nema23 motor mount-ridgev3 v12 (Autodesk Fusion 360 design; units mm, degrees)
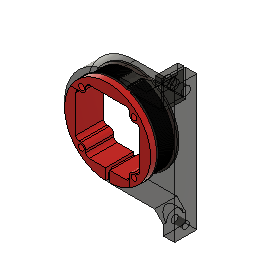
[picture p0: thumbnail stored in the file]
parameter "d58" = -1
parameter "d59" = -1
parameter "d60" = -1
parameter "d61" = -1
parameter "d62" = 4
parameter "d63" = 25.5
parameter "d66" = 16.5 (= "d67")
parameter "d67" = 16.5
parameter "d68" = 3
parameter "d81" = 16.5 (= "d67")
parameter "d89" = 28.5
parameter "d93" = 23.5
sketch "Sketch1" plane through (0, 0, 37.5) normal (0, 0, 1) x axis (1, 0, 0)
  line L1 (45, -43.5) -> (0, -43.5)
  line L2 (45, -60.5) -> (45, -43.5)
  line L3 (55, -60.5) -> (45, -60.5)
  line L4 (45, 35.8891) -> (45, 60.5)
  line L5 (55, 60.5) -> (45, 60.5)
  line L6 (55, -60.5) -> (55, 60.5)
  line L7 (43, 37) -> (0, 37)
  line L8 (43, 60.5) -> (43, 37)
  line L9 (38, 60.5) -> (43, 60.5)
  line L10 (38, 43.5) -> (38, 60.5)
  line L11 (45, 35.8891) -> (8.9984, 35.8891)
  line L12 (44, 56) -> (44, 55)
  line L13 (38, 43.5) -> (0, 43.5)
  circle C1 centre (0, 0) radius 38.5
  circle C2 centre (0, 0) radius 37
  arc A1 centre (0, 0) radius 43.5 clockwise from (24.5809, 35.8891) to (22.8747, 37)
  point P1 (0, 0)
  point P2 (0, 0)
  point P4 (0, 43.5)
  point P5 (0, -43.5)
  point P12 (0, 37)
  point P20 (24.5809, 35.8891)
  point P21 (22.8747, 37)
  point P22 (8.9984, 35.8891)
  point P7 (45, -60.5)
  point P8 (55, -60.5)
  point P13 (43, 37)
  point P6 (45, -43.5)
  point P3 (0, 0)
  point P10 (55, 60.5)
  point P9 (45, 60.5)
  point P14 (43, 60.5)
  point P15 (38, 60.5)
  coincident P1 P2
  coincident P4 A1
  horizontal L13
  coincident P5 A1
  horizontal L1
  perpendicular L1 L2
  perpendicular L2 L3
  perpendicular L4 L13
  perpendicular L4 L5
  perpendicular L3 L6
  coincident C2 P12
  horizontal L7
  perpendicular L7 L8
  perpendicular L8 L9
  perpendicular L10 L13
  parallel L7 L11
  coincident L11 P20
  coincident L7 P21
  coincident C2 P22
  dimension "d1" diameter C1 = 77
  dimension "d2" diameter A1 = 87
  dimension "d3" distance P7 P8 = 10
  dimension "d4" diameter C2 = 74
  dimension "d15" distance P12 P13 = 43
  dimension "d50" distance P6 P7 = 17
  dimension "d214" distance P3 L1 = 43.5
  dimension "d216" distance L1 L13 = 87 (= "d214 * 2")
  dimension "d217" distance P8 P10 = 121 (= "d216 + ( d50 * 2 )")
  dimension "d218" distance L3 L9 = 121 (= "d217")
  dimension "d219" distance P9 P10 = 10 (= "d3")
  dimension "d220" distance P14 P15 = 5
sketch "Sketch9" plane through (0, 0, 37.5) normal (0, 0, 1) x axis (1, 0, 0)
  line L1 (19.5, -23.5) -> (19.5, -25.5)
  line L2 (19.5, 25.5) -> (19.5, 23.5)
  line L3 (23.5, 19.5) -> (25.5, 19.5)
  line L4 (25.5, -19.5) -> (23.5, -19.5)
  line L5 (28.5, 16.5) -> (28.5, -16.5033)
  line L6 (-19.5, 23.5) -> (-19.5, 25.5)
  line L7 (-16.5, 28.5) -> (16.5, 28.5)
  line L8 (-25.5, 19.5) -> (-23.5, 19.5)
  line L9 (-19.5, -25.5) -> (-19.5, -23.5)
  line L10 (-23.5, -19.5) -> (-25.5038, -19.5)
  line L11 (-28.5, -16.6505) -> (-28.5, 16.5)
  line L12 (16.5, -28.5) -> (-16.5, -28.5)
  arc A1 centre (23.5, 23.5) radius 4 clockwise from (23.5, 19.5) to (19.5, 23.5)
  arc A2 centre (25.5, 16.5) radius 3 clockwise from (25.5, 19.5) to (28.5, 16.5)
  arc A3 centre (16.5, -25.5) radius 3 clockwise from (19.5, -25.5) to (16.5, -28.5)
  arc A4 centre (25.5, -16.5) radius 3 clockwise from (28.5, -16.5033) to (25.5, -19.5)
  arc A5 centre (23.5, -23.5) radius 4 clockwise from (19.5, -23.5) to (23.5, -19.5)
  arc A6 centre (16.5, 25.5) radius 3 clockwise from (16.5, 28.5) to (19.5, 25.5)
  arc A7 centre (-23.5, 23.5) radius 4 clockwise from (-19.5, 23.5) to (-23.5, 19.5)
  arc A8 centre (-25.5, 16.5) radius 3 clockwise from (-28.5, 16.5) to (-25.5, 19.5)
  arc A9 centre (-23.5, -23.5) radius 4 clockwise from (-23.5, -19.5) to (-19.5, -23.5)
  arc A10 centre (-25.5038, -16.5) radius 3 clockwise from (-25.5038, -19.5) to (-28.5, -16.6505)
  arc A11 centre (-16.5, -25.5) radius 3 clockwise from (-16.5, -28.5) to (-19.5, -25.5)
  arc A12 centre (-16.5, 25.5) radius 3 clockwise from (-19.5, 25.5) to (-16.5, 28.5)
  point P10 (0, 0)
  point P13 (-16.5, -25.5)
  point P11 (16.5, -25.5)
  point P26 (-25.5038, -16.5)
  point P23 (-25.5, 16.5)
  point P22 (25.5, 16.5)
  point P15 (25.5, -16.5)
  point P27 (-16.5, 25.5)
  point P7 (16.5, 25.5)
  point P36 (-23.5, -23.5)
  point P4 (-23.5, 23.5)
  point P9 (23.5, 23.5)
  point P34 (23.5, -23.5)
  dimension "d142" radius A9 = 4
  dimension "d143" distance P10 P13 = 25.5
  dimension "d144" distance P10 P11 = 25.5
  dimension "d145" distance P10 P11 = 16.5 (= "d66")
  dimension "d146" distance P10 P13 = 16.5 (= "d67")
  dimension "d147" distance P10 P26 = 16.5
  dimension "d148" radius A10 = 3
  dimension "d149" radius A11 = 3 (= "d68")
  dimension "d150" radius A6 = 3 (= "d68")
  dimension "d151" radius A2 = 3 (= "d68")
  dimension "d152" radius A4 = 3 (= "d68")
  dimension "d153" radius A12 = 3 (= "d68")
  dimension "d154" radius A8 = 3 (= "d68")
  dimension "d155" radius A3 = 3 (= "d68")
  dimension "d156" radius A5 = 4 (= "d62")
  dimension "d157" radius A7 = 4 (= "d62")
  dimension "d158" radius A1 = 4 (= "d62")
  dimension "d159" distance P10 P23 = 25.5 (= "d63")
  dimension "d160" distance P10 P22 = 25.5 (= "d63")
  dimension "d161" distance P10 P23 = 16.5 (= "d67")
  dimension "d162" distance P10 P22 = 16.5 (= "d67")
  dimension "d163" distance P10 P15 = 16.5 (= "d67")
  dimension "d164" distance P10 P15 = 25.5 (= "d63")
  dimension "d165" distance P10 P27 = 16.5 (= "d81")
  dimension "d166" distance P7 P10 = 16.5 (= "d67")
  dimension "d167" distance P7 P10 = 25.5 (= "d63")
  dimension "d168" distance P10 P27 = 25.5 (= "d63")
  dimension "d169" distance P10 L11 = 28.5
  dimension "d170" distance P10 L5 = 28.5 (= "d89")
  dimension "d171" distance P10 L7 = 28.5 (= "d89")
  dimension "d172" distance P10 L12 = 28.5 (= "d89")
  dimension "d173" distance P10 P36 = 23.5
  dimension "d174" distance P10 P36 = 23.5 (= "d93")
  dimension "d175" distance P4 P10 = 23.5 (= "d93")
  dimension "d176" distance P4 P10 = 23.5 (= "d93")
  dimension "d177" distance P9 P10 = 23.5 (= "d93")
  dimension "d178" distance P9 P10 = 23.5 (= "d93")
  dimension "d179" distance P10 P34 = 23.5 (= "d93")
  dimension "d180" distance P10 P34 = 23.5 (= "d93")
extrude "Extrude1" new body sketch "Sketch1" profile of C1 C2 L7 L11 against normal blind 25 and along normal blind 5
extrude "Extrude10" cut sketch "Sketch9" against normal blind 35 and along normal blind 10
sketch "Sketch2" plane through (0, 0, 0) normal (1, 0, 0) x axis (0, 0, -1)
  line L1 (-34.2758, 36.8725) -> (-20.6956, 36.8725)
  line L2 (-34.2758, 36.8725) -> (-36.3959, 38.9926)
  line L3 (-33.9025, 38.9926) -> (-36.3959, 38.9926)
  line L4 (-20.6956, 36.8725) -> (-18.5755, 38.9926)
  line L5 (-36.3959, 38.9926) -> (-18.5755, 38.9926)
  point P1 (0, 0)
  horizontal L3
  dimension "d12" angle L2 L3 = 45
  dimension "d13" angle L2 L4 = 90
  dimension "d52" distance P1 L1 = 36.8725 (= "35.872502 mm + 1 mm")
revolve "Revolve1" sketch "Sketch2" AlongAngle 360
sketch "Sketch10" plane through (0, 0, 42.5) normal (0, 0, 1) x axis (1, 0, 0)
  line L1 (19.5, 23.5) -> (19.5, 25.5)
  line L2 (25.5, 19.5) -> (23.5, 19.5)
  line L3 (28.5, -16.5033) -> (28.5, 16.5)
  line L4 (23.5, -19.5) -> (25.5, -19.5)
  line L5 (19.5, -25.5) -> (19.5, -23.5)
  line L6 (-16.5, -28.5) -> (16.5, -28.5)
  line L7 (-19.5, -23.5) -> (-19.5, -25.5)
  line L8 (-25.5038, -19.5) -> (-23.5, -19.5)
  line L9 (-28.5, 16.5) -> (-28.5, -16.6505)
  line L10 (-23.5, 19.5) -> (-25.5, 19.5)
  line L11 (-19.5, 25.5) -> (-19.5, 23.5)
  line L12 (16.5, 28.5) -> (-16.5, 28.5)
  circle C1 centre (0, 0) radius 38.5
  circle C2 centre (0, 36.8) radius 0.25
  circle C3 centre (0.5, 36.8) radius 0.25
  arc A1 centre (16.5, 25.5) radius 3 clockwise from (16.5, 28.5) to (19.5, 25.5)
  arc A2 centre (23.5, 23.5) radius 4 clockwise from (23.5, 19.5) to (19.5, 23.5)
  arc A3 centre (25.5, 16.5) radius 3 clockwise from (25.5, 19.5) to (28.5, 16.5)
  arc A4 centre (25.5, -16.5) radius 3 clockwise from (28.5, -16.5033) to (25.5, -19.5)
  arc A5 centre (23.5, -23.5) radius 4 clockwise from (19.5, -23.5) to (23.5, -19.5)
  arc A6 centre (16.5, -25.5) radius 3 clockwise from (19.5, -25.5) to (16.5, -28.5)
  arc A7 centre (-16.5, -25.5) radius 3 clockwise from (-16.5, -28.5) to (-19.5, -25.5)
  arc A8 centre (-23.5, -23.5) radius 4 clockwise from (-23.5, -19.5) to (-19.5, -23.5)
  arc A9 centre (-25.5038, -16.5) radius 3 clockwise from (-25.5038, -19.5) to (-28.5, -16.6505)
  arc A10 centre (-25.5, 16.5) radius 3 clockwise from (-28.5, 16.5) to (-25.5, 19.5)
  arc A11 centre (-23.5, 23.5) radius 4 clockwise from (-19.5, 23.5) to (-23.5, 19.5)
  arc A12 centre (-16.5, 25.5) radius 3 clockwise from (-19.5, 25.5) to (-16.5, 28.5)
  point P3 (0, 36.8)
  point P4 (0, 0)
  point P5 (0.5, 36.8)
  point P1 (0, 0)
  dimension "d188" diameter C2 = 0.5
  dimension "d189" distance P3 P4 = 36.8
  dimension "d193" diameter C3 = 0.5 (= "d188")
  dimension "d194" distance P3 P5 = 0.5 (= "d188")
  dimension "d195" distance P1 P5 = 36.8 (= "d189")
extrude "Extrude13" add sketch "Sketch10" profile of C2 no distance stored
extrude "Extrude14" cut sketch "Sketch10" profile of C2 C3 blind -14 from offset -3
circular_pattern "C-Pattern1" countU 232 TotalAngle 360
extrude "Extrude2" new body sketch "Sketch1" profile of C1 A1 L13 L1 L2 L3 L4 L5 L6 C2 L7 L8 L9 L10 L11 against normal blind 20
combine "Combine4"
sketch "Sketch6" plane through (0, 0, 12.5) normal (0, 0, -1) x axis (-1, 0, 0)
  line L1 (16.5, 28.5) -> (-16.5, 28.5)
  line L2 (19.5, 23.5) -> (19.5, 25.5)
  line L3 (25.5, 19.5) -> (23.5, 19.5)
  line L4 (28.5, -16.6505) -> (28.5, 16.5)
  line L5 (23.5, -19.5) -> (25.5038, -19.5)
  line L6 (19.5, -25.5) -> (19.5, -23.5)
  line L7 (-16.5, -28.5) -> (16.5, -28.5)
  line L8 (-19.5, -23.5) -> (-19.5, -25.5)
  line L9 (-25.5, -19.5) -> (-23.5, -19.5)
  line L10 (-28.5, 16.5) -> (-28.5, -16.5033)
  line L11 (-23.5, 19.5) -> (-25.5, 19.5)
  line L12 (-19.5, 25.5) -> (-19.5, 23.5)
  circle C1 centre (0, 0) radius 38.5
  arc A1 centre (-16.5, 25.5) radius 3 clockwise from (-19.5, 25.5) to (-16.5, 28.5)
  arc A2 centre (16.5, 25.5) radius 3 clockwise from (16.5, 28.5) to (19.5, 25.5)
  arc A3 centre (23.5, 23.5) radius 4 clockwise from (23.5, 19.5) to (19.5, 23.5)
  arc A4 centre (25.5, 16.5) radius 3 clockwise from (25.5, 19.5) to (28.5, 16.5)
  arc A5 centre (25.5038, -16.5) radius 3 clockwise from (28.5, -16.6505) to (25.5038, -19.5)
  arc A6 centre (23.5, -23.5) radius 4 clockwise from (19.5, -23.5) to (23.5, -19.5)
  arc A7 centre (16.5, -25.5) radius 3 clockwise from (19.5, -25.5) to (16.5, -28.5)
  arc A8 centre (-16.5, -25.5) radius 3 clockwise from (-16.5, -28.5) to (-19.5, -25.5)
  arc A9 centre (-23.5, -23.5) radius 4 clockwise from (-23.5, -19.5) to (-19.5, -23.5)
  arc A10 centre (-25.5, -16.5) radius 3 clockwise from (-25.5, -19.5) to (-28.5, -16.5033)
  arc A11 centre (-25.5, 16.5) radius 3 clockwise from (-28.5, 16.5) to (-25.5, 19.5)
  arc A12 centre (-23.5, 23.5) radius 4 clockwise from (-19.5, 23.5) to (-23.5, 19.5)
offset_faces "OffsetFaces2" distance -0.001
offset_faces "OffsetFaces4" distance -0.3
offset_faces "OffsetFaces5" distance -0.4
sketch "Sketch3" plane through (0, 0, 42.5) normal (0, 0, 1) x axis (1, 0, 0)
  line L1 (19.501, 23.5) -> (19.501, 25.5)
  line L2 (25.5, 19.501) -> (23.5, 19.501)
  line L3 (28.501, -16.5033) -> (28.501, 16.5)
  line L4 (23.5, -19.501) -> (25.5, -19.501)
  line L5 (19.501, -25.5) -> (19.501, -23.5)
  line L6 (-16.5, -28.501) -> (16.5, -28.501)
  line L7 (-19.501, -23.5) -> (-19.501, -25.5)
  line L8 (-25.5038, -19.501) -> (-23.5, -19.501)
  line L9 (-28.501, 16.5) -> (-28.501, -16.6506)
  line L10 (-23.5, 19.501) -> (-25.5, 19.501)
  line L11 (-19.501, 25.5) -> (-19.501, 23.5)
  line L12 (16.5, 28.501) -> (-16.5, 28.501)
  circle C1 centre (0, 0) radius 38.5
  circle C2 centre (-23.5, -23.5) radius 2.55
  circle C3 centre (23.5, -23.5) radius 2.55
  circle C4 centre (-23.5, 23.5) radius 2.55
  circle C5 centre (23.5, 23.5) radius 2.55
  arc A1 centre (16.5, 25.5) radius 3.001 clockwise from (16.5, 28.501) to (19.501, 25.5)
  arc A2 centre (23.5, 23.5) radius 3.999 clockwise from (23.5, 19.501) to (19.501, 23.5)
  arc A3 centre (25.5, 16.5) radius 3.001 clockwise from (25.5, 19.501) to (28.501, 16.5)
  arc A4 centre (25.5, -16.5) radius 3.001 clockwise from (28.501, -16.5033) to (25.5, -19.501)
  arc A5 centre (23.5, -23.5) radius 3.999 clockwise from (19.501, -23.5) to (23.5, -19.501)
  arc A6 centre (16.5, -25.5) radius 3.001 clockwise from (19.501, -25.5) to (16.5, -28.501)
  arc A7 centre (-16.5, -25.5) radius 3.001 clockwise from (-16.5, -28.501) to (-19.501, -25.5)
  arc A8 centre (-23.5, -23.5) radius 3.999 clockwise from (-23.5, -19.501) to (-19.501, -23.5)
  arc A9 centre (-25.5038, -16.5) radius 3.001 clockwise from (-25.5038, -19.501) to (-28.501, -16.6506)
  arc A10 centre (-25.5, 16.5) radius 3.001 clockwise from (-28.501, 16.5) to (-25.5, 19.501)
  arc A11 centre (-23.5, 23.5) radius 3.999 clockwise from (-19.501, 23.5) to (-23.5, 19.501)
  arc A12 centre (-16.5, 25.5) radius 3.001 clockwise from (-19.501, 25.5) to (-16.5, 28.501)
  dimension "d20" diameter C2 = 5.1
  dimension "d21" diameter C3 = 5.1 (= "d20")
  dimension "d22" diameter C4 = 5.1 (= "d20")
  dimension "d23" diameter C5 = 5.1 (= "d20")
extrude "Extrude3" cut sketch "Sketch3" profile of C2 C3 C4 C5 to an object
sketch "bolt holes" plane through (45, 0, 0) normal (-1, 0, 0) x axis (0, 0, 1)
  line L1 (37.5, -43.5) -> (37.5, -60.5)
  line L2 (17.5, -43.5) -> (37.5, -43.5)
  line L3 (17.5, -60.5) -> (17.5, -43.5)
  line L4 (37.5, -60.5) -> (17.5, -60.5)
  line L5 (37.5, 43.5) -> (37.5, 60.5)
  line L6 (17.5, 60.5) -> (37.5, 60.5)
  circle C1 centre (27.5, -52) radius 3.1
  circle C2 centre (27.5, 52) radius 4.1
  circle C3 centre (27.5, 52) radius 7.75
  circle C4 centre (27.5, -52) radius 7.75
  point P6 (27.5, -52)
  point P7 (27.5, 52)
  concentric C2 C3
  concentric C1 C4
  dimension "d26" diameter C1 = 6.2
  dimension "d27" distance L2 L4 = 17
  dimension "d28" distance L4 P6 = 8.5 (= "d27 / 2")
  dimension "d29" distance L1 P6 = 10
  dimension "d30" diameter C2 = 8.2
  dimension "d31" distance P7 L5 = 10
  dimension "d32" distance P7 L6 = 8.5 (= "d28")
  dimension "d33" diameter C3 = 15.5 (= "d34")
  dimension "d34" diameter C4 = 15.5
extrude "Extrude4" cut sketch "bolt holes" profile of C1 C2 along normal blind 7 and against normal blind 15
chamfer "Chamfer1" distance 8
extrude "Extrude5" cut sketch "bolt holes" profile of C1 C4 along normal blind 30
extrude "Extrude6" cut sketch "bolt holes" profile of C2 C3 blind 15 from offset 7
sketch "Sketch5" plane through (0, 0, 42.5) normal (0, 0, 1) x axis (1, 0, 0)
  line L1 (19.5, -35) -> (19.5, -24.5)
  line L2 (-19.5, 35) -> (-19.5, 24.5)
  line L3 (-35, 19.5) -> (-24.5, 19.5)
  line L4 (38, -19.5) -> (24.5, -19.5)
  line L5 (19.501, 23.5) -> (19.501, 25.5)
  line L6 (25.5, 19.501) -> (23.5, 19.501)
  line L7 (28.501, -16.5033) -> (28.501, 16.5)
  line L8 (23.5, -19.501) -> (25.5, -19.501)
  line L9 (19.501, -25.5) -> (19.501, -23.5)
  line L10 (-16.5, -28.501) -> (16.5, -28.501)
  line L11 (-19.501, -23.5) -> (-19.501, -25.5)
  line L12 (-25.5038, -19.501) -> (-23.5, -19.501)
  line L13 (-28.501, 16.5) -> (-28.501, -16.6506)
  line L14 (-23.5, 19.501) -> (-25.5, 19.501)
  line L15 (-19.501, 25.5) -> (-19.501, 23.5)
  line L16 (16.5, 28.501) -> (-16.5, 28.501)
  circle C1 centre (23.5, 23.5) radius 2.55
  circle C2 centre (23.5, -23.5) radius 2.55
  circle C3 centre (-23.5, 23.5) radius 2.55
  circle C4 centre (-23.5, -23.5) radius 2.55
  circle C5 centre (0, 0) radius 38.5
  arc A1 centre (16.5, 25.5) radius 3.001 clockwise from (16.5, 28.501) to (19.501, 25.5)
  arc A2 centre (23.5, 23.5) radius 3.999 clockwise from (23.5, 19.501) to (19.501, 23.5)
  arc A3 centre (25.5, 16.5) radius 3.001 clockwise from (25.5, 19.501) to (28.501, 16.5)
  arc A4 centre (25.5, -16.5) radius 3.001 clockwise from (28.501, -16.5033) to (25.5, -19.501)
  arc A5 centre (23.5, -23.5) radius 3.999 clockwise from (19.501, -23.5) to (23.5, -19.501)
  arc A6 centre (16.5, -25.5) radius 3.001 clockwise from (19.501, -25.5) to (16.5, -28.501)
  arc A7 centre (-16.5, -25.5) radius 3.001 clockwise from (-16.5, -28.501) to (-19.501, -25.5)
  arc A8 centre (-23.5, -23.5) radius 3.999 clockwise from (-23.5, -19.501) to (-19.501, -23.5)
  arc A9 centre (-25.5038, -16.5) radius 3.001 clockwise from (-25.5038, -19.501) to (-28.501, -16.6506)
  arc A10 centre (-25.5, 16.5) radius 3.001 clockwise from (-28.501, 16.5) to (-25.5, 19.501)
  arc A11 centre (-23.5, 23.5) radius 3.999 clockwise from (-19.501, 23.5) to (-23.5, 19.501)
  arc A12 centre (-16.5, 25.5) radius 3.001 clockwise from (-19.501, 25.5) to (-16.5, 28.501)
extrude "Extrude11" cut sketch "Sketch5" profile of C1 C5 L2 L4 A1 L5 A2 L6 A3 L7 A4 A12 L16 against normal blind 30
extrude "Extrude12" cut sketch "Sketch5" profile of C1 C2 C3 C4 C5 L1 L2 L3 L4 A4 L8 A5 L9 A6 A10 L14 A11 L15 A12 against normal blind 15
copy_paste_bodies "CopyPasteBodies6"
move "Move1"
move "Move2"
move "Move3"
sketch "Sketch11" plane through (0, 0, 12.5) normal (0, 0, -1) x axis (-1, 0, 0)
  line L1 (-33.1964, -19.5) -> (-25.5774, -19.5)
  line L2 (19.5, 25.5773) -> (19.5, 33.1964)
  line L3 (19.501, 23.5) -> (19.501, 25.5)
  line L4 (25.5, 19.501) -> (23.5, 19.501)
  line L5 (28.501, -16.6506) -> (28.501, 16.5)
  line L6 (23.5, -19.501) -> (25.5038, -19.501)
  line L7 (19.501, -25.5) -> (19.501, -23.5)
  line L8 (-16.5, -28.501) -> (16.5, -28.501)
  line L9 (-19.501, -23.5) -> (-19.501, -25.5)
  line L10 (-25.5, -19.501) -> (-23.5, -19.501)
  line L11 (1.9505, -28.501) -> (-2.0495, -28.501)
  line L12 (1.9505, -31.001) -> (1.9505, -28.501)
  line L13 (-2.0495, -31.001) -> (1.9505, -31.001)
  line L14 (-2.0495, -28.501) -> (-2.0495, -31.001)
  arc A1 centre (0, 0) radius 38.5 clockwise from (19.5, 33.1964) to (-33.1964, -19.5)
  arc A2 centre (16.5, 25.5) radius 3.001 clockwise from (19.5, 25.5773) to (19.501, 25.5)
  arc A3 centre (23.5, 23.5) radius 3.999 clockwise from (23.5, 19.501) to (19.501, 23.5)
  arc A4 centre (25.5, 16.5) radius 3.001 clockwise from (25.5, 19.501) to (28.501, 16.5)
  arc A5 centre (25.5038, -16.5) radius 3.001 clockwise from (28.501, -16.6506) to (25.5038, -19.501)
  arc A6 centre (23.5, -23.5) radius 3.999 clockwise from (19.501, -23.5) to (23.5, -19.501)
  arc A7 centre (16.5, -25.5) radius 3.001 clockwise from (19.501, -25.5) to (16.5, -28.501)
  arc A8 centre (-16.5, -25.5) radius 3.001 clockwise from (-16.5, -28.501) to (-19.501, -25.5)
  arc A9 centre (-23.5, -23.5) radius 3.999 clockwise from (-23.5, -19.501) to (-19.501, -23.5)
  arc A10 centre (-25.5, -16.5) radius 3.001 clockwise from (-25.5, -19.501) to (-25.5774, -19.5)
  circle C1 centre (23.5, -23.5) radius 2.55
  circle C2 centre (23.5, 23.5) radius 2.55
  circle C3 centre (-23.5, -23.5) radius 2.55
  point P32 (-2.0495, -28.501)
  point P33 (1.9505, -28.501)
  point P35 (-2.0495, -31.001)
  horizontal L11
  vertical L12
  horizontal L13
  vertical L14
  coincident L8 P32
  dimension "d205" distance P32 P33 = 4
  dimension "d206" distance P32 P35 = 2.5
extrude "Extrude15" cut sketch "Sketch11" profile of L8 L11 L12 L13 L14 against normal blind 45
sketch "Sketch12" plane through (0, -31.001, 0) normal (0, 1, 0) x axis (-1, 0, 0)
  line L1 (-2.0495, 42.5) -> (1.9505, 42.5)
  line L2 (-2.0495, 12.5) -> (-2.0495, 42.5)
  line L3 (1.9505, 12.5) -> (-2.0495, 12.5)
  line L4 (1.9505, 42.5) -> (1.9505, 12.5)
  line L5 (1.9505, 42.5) -> (-2.0495, 42.5)
  line L6 (1.9505, 40) -> (1.9505, 42.5)
  line L7 (-2.0495, 40) -> (1.9505, 40)
  line L8 (-2.0495, 42.5) -> (-2.0495, 40)
  point P3 (-2.0495, 42.5)
  point P6 (-2.0495, 42.5)
  point P7 (1.9505, 42.5)
  horizontal L5
  vertical L6
  horizontal L7
  vertical L8
  coincident P3 P6
  dimension "d209" distance P6 P7 = 4
extrude "Extrude16" cut sketch "Sketch12" profile of L1 L2 L4 L5 L6 L7 L8 against normal blind 11.5
chamfer "Chamfer2" distance 3
offset_faces "OffsetFaces6" distance -5
offset_faces "OffsetFaces7" distance -5
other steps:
base_feature "Base Feature"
